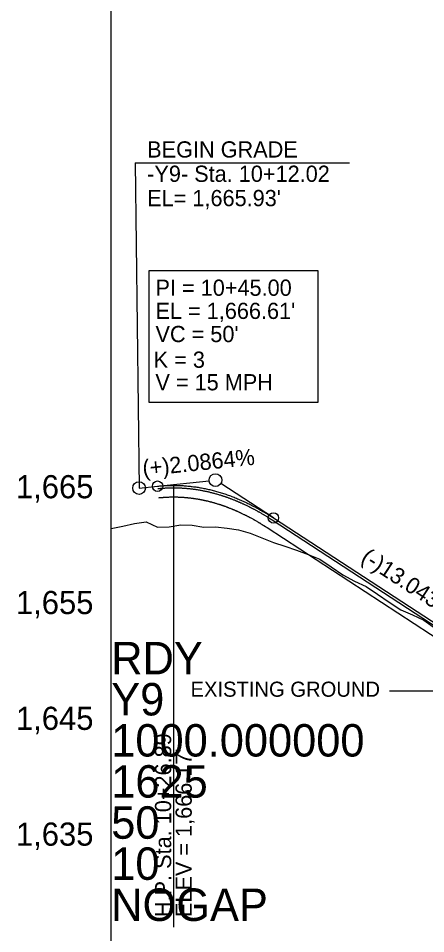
# Model space of a CAD drawing. Extents: x 498575 to 532350, y 405181 to 484585.
# Drawn here: x 505816.6 to 505992.5, y 449850.6 to 450245.8 of the extents above; entities that cross this region are included whole.
import ezdxf

# ---------------------------------------------------------------- set-up
doc = ezdxf.new("R2010")
doc.units = 0
for name, color, linetype in [('Exist Profile Cell', 7, 'Continuous'), ('Exist Vertical Profile Ground Line', 7, 'Continuous'), ('Exist Vertical Profile Vertical Axis Label', 7, 'Continuous'), ('Prop Grid Mask', 7, 'Continuous'), ('Prop PFL Text', 7, 'Continuous'), ('Prop Vertical Profile Curve Label', 7, 'Continuous'), ('Prop Vertical Profile Grade', 7, 'Continuous'), ('Prop Vertical Profile Grade Label', 7, 'Continuous'), ('Prop Vertical Profile Strip Grade', 7, 'Continuous'), ('Prop VPI Label', 7, 'Continuous'), ('Scratch_Level_5', 7, 'Continuous')]:
    doc.layers.add(name, color=color, linetype=linetype)

msp = doc.modelspace()

# ---------------------------------------------------------------- linework, layer by layer
at = {"layer": 'Exist Profile Cell'}
msp.add_line((505856.74, 449838.32), (505856.74, 451088.32), dxfattribs=at)
at = {"layer": 'Exist Vertical Profile Ground Line'}
msp.add_lwpolyline([(505856.74, 450025.46), (505861.74, 450026.58), (505866.74, 450027.62), (505871.74, 450028.47), (505876.74, 450026.08), (505881.74, 450026.18), (505886.74, 450027.05), (505891.74, 450026.9), (505896.74, 450026.1), (505901.74, 450026.27), (505906.74, 450025.71), (505911.74, 450024.91), (505916.74, 450023.57), (505921.74, 450021.47), (505926.74, 450019.48), (505931.74, 450017.95), (505936.74, 450016.24), (505941.74, 450014.28), (505946.74, 450012.24), (505951.74, 450009.02), (505956.74, 450005.57), (505961.74, 450002.85), (505966.74, 450000.46), (505971.74, 449997.13), (505976.74, 449993.78), (505981.74, 449990.43), (505986.74, 449988.29), (505991.74, 449986), (505996.74, 449982.39)], dxfattribs=at)
at = {"layer": 'Prop Grid Mask'}
msp.add_lwpolyline([(505872.99, 450080.05), (505946, 450080.05), (505946, 450136.83), (505872.99, 450136.83)], close=True, dxfattribs=at)
at = {"layer": 'Prop PFL Text'}
msp.add_line((505976.83, 449955.42), (505997.2, 449955.42), dxfattribs=at)
at = {"layer": 'Prop Vertical Profile Curve Label'}
for centre in [(505876.74, 450043.79), (505926.74, 450030.09)]:
    msp.add_circle(centre, 2.25, dxfattribs=at)
at = {"layer": 'Prop Vertical Profile Grade'}
for p, q in [((505868.76, 450042.96), (505876.74, 450043.79)), ((505926.74, 450030.09), (506021.74, 449968.14))]:
    msp.add_line(p, q, dxfattribs=at)
msp.add_spline([(505876.74, 450043.79), (505877.74, 450043.89), (505878.74, 450043.97), (505879.74, 450044.04), (505880.74, 450044.09), (505881.74, 450044.12), (505882.74, 450044.14), (505883.74, 450044.15), (505884.74, 450044.14), (505885.74, 450044.12), (505886.74, 450044.08), (505887.74, 450044.02), (505888.74, 450043.95), (505889.74, 450043.87), (505890.74, 450043.77), (505891.74, 450043.65), (505892.74, 450043.52), (505893.74, 450043.38), (505894.74, 450043.22), (505895.74, 450043.04), (505896.74, 450042.85), (505897.74, 450042.64), (505898.74, 450042.42), (505899.74, 450042.19), (505900.74, 450041.94), (505901.74, 450041.67), (505902.74, 450041.39), (505903.74, 450041.09), (505904.74, 450040.78), (505905.74, 450040.45), (505906.74, 450040.11), (505907.74, 450039.75), (505908.74, 450039.38), (505909.74, 450038.99), (505910.74, 450038.59), (505911.74, 450038.17), (505912.74, 450037.74), (505913.74, 450037.29), (505914.74, 450036.83), (505915.74, 450036.35), (505916.74, 450035.86), (505917.74, 450035.35), (505918.74, 450034.83), (505919.74, 450034.29), (505920.74, 450033.73), (505921.74, 450033.17), (505922.74, 450032.58), (505923.74, 450031.98), (505924.74, 450031.37), (505925.74, 450030.74), (505926.74, 450030.09)], degree=3, dxfattribs=at)
at = {"layer": 'Prop Vertical Profile Strip Grade'}
msp.add_line((505883.63, 450044.15), (505883.63, 449853.36), dxfattribs=at)
at = {"layer": 'Prop VPI Label'}
for p, q in [((505867.05, 450183.41), (505868.76, 450042.96)), ((505867.05, 450183.41), (505959.57, 450183.41)), ((505876.74, 450043.79), (505899, 450046.11)), ((505926.74, 450030.09), (505904.04, 450044.9))]:
    msp.add_line(p, q, dxfattribs=at)
for centre in [(505868.76, 450042.96), (505901.74, 450046.4)]:
    msp.add_circle(centre, 2.75, dxfattribs=at)
at = {"layer": 'Scratch_Level_5'}
for p, q in [((505924.01, 450025.91), (506019.01, 449963.95)), ((505926.17, 450029.22), (506021.17, 449967.26))]:
    msp.add_line(p, q, dxfattribs=at)
for points in [[(505876.84, 450042.75), (505877.11, 450042.78), (505877.42, 450042.81), (505877.75, 450042.84), (505877.8, 450042.85), (505877.83, 450042.85), (505877.83, 450042.85), (505877.84, 450042.85), (505877.85, 450042.85), (505877.92, 450042.86), (505878, 450042.87), (505878.2, 450042.88), (505878.33, 450042.89), (505878.53, 450042.91), (505878.6, 450042.91), (505878.7, 450042.92), (505878.74, 450042.92), (505878.78, 450042.93), (505878.79, 450042.93), (505878.81, 450042.93), (505878.82, 450042.93), (505878.84, 450042.93), (505878.99, 450042.94), (505879.42, 450042.97), (505879.82, 450043), (505880.63, 450043.04), (505881.18, 450043.06), (505882.26, 450043.1), (505882.8, 450043.11), (505883.89, 450043.11), (505884.43, 450043.11), (505885.51, 450043.08), (505886.06, 450043.07), (505887.14, 450043.02), (505887.68, 450042.98), (505888.76, 450042.91), (505889.3, 450042.86), (505890.38, 450042.76), (505890.92, 450042.7), (505891.73, 450042.61), (505892, 450042.57), (505892.54, 450042.5), (505892.81, 450042.46), (505893.61, 450042.35), (505894.15, 450042.26), (505895.22, 450042.08), (505895.75, 450041.98), (505896.55, 450041.83), (505896.82, 450041.77), (505897.35, 450041.66), (505897.61, 450041.61), (505898.41, 450041.43), (505898.94, 450041.31), (505899.73, 450041.12), (505899.99, 450041.05), (505900.52, 450040.92), (505900.78, 450040.85), (505901.57, 450040.64), (505902.09, 450040.49), (505903.14, 450040.19), (505903.66, 450040.03), (505904.43, 450039.78), (505904.69, 450039.7), (505905.21, 450039.53), (505905.47, 450039.45), (505905.98, 450039.27), (505906.24, 450039.18), (505906.75, 450039), (505907.26, 450038.82), (505907.77, 450038.63), (505908.28, 450038.44), (505908.54, 450038.34), (505909.3, 450038.05), (505909.8, 450037.85), (505910.43, 450037.59), (505910.56, 450037.54), (505910.81, 450037.44), (505911.19, 450037.28), (505911.56, 450037.12), (505912.06, 450036.9), (505912.31, 450036.79), (505912.81, 450036.57), (505913.31, 450036.35), (505913.8, 450036.12), (505914.29, 450035.89), (505914.54, 450035.77), (505915.28, 450035.42), (505915.77, 450035.18), (505916.38, 450034.88), (505916.5, 450034.82), (505916.74, 450034.69), (505917.1, 450034.51), (505917.47, 450034.32), (505917.95, 450034.07), (505918.19, 450033.94), (505918.67, 450033.68), (505919.15, 450033.42), (505919.75, 450033.1), (505920.11, 450032.9), (505920.34, 450032.76), (505920.46, 450032.7), (505921.06, 450032.36), (505921.53, 450032.09), (505922.23, 450031.67), (505922.47, 450031.53), (505922.94, 450031.25), (505923.4, 450030.97), (505923.9, 450030.67), (505924.16, 450030.5), (505924.19, 450030.48), (505924.2, 450030.48), (505924.21, 450030.47), (505924.24, 450030.45), (505924.32, 450030.4), (505924.39, 450030.36), (505924.56, 450030.25), (505924.68, 450030.18), (505924.91, 450030.03), (505925.02, 450029.96), (505925.14, 450029.88), (505925.15, 450029.88), (505925.16, 450029.87), (505925.17, 450029.87), (505925.17, 450029.86), (505925.19, 450029.85), (505925.23, 450029.82), (505925.34, 450029.76), (505925.65, 450029.55), (505925.94, 450029.37), (505926.18, 450029.22)], [(505877.22, 450038.81), (505877.5, 450038.84), (505877.8, 450038.87), (505878.13, 450038.9), (505878.19, 450038.91), (505878.21, 450038.91), (505878.22, 450038.91), (505878.22, 450038.91), (505878.22, 450038.91), (505878.22, 450038.91), (505878.23, 450038.91), (505878.24, 450038.91), (505878.3, 450038.92), (505878.35, 450038.92), (505878.52, 450038.94), (505878.64, 450038.95), (505878.83, 450038.96), (505878.9, 450038.97), (505879, 450038.97), (505879.03, 450038.98), (505879.07, 450038.98), (505879.09, 450038.98), (505879.1, 450038.98), (505879.11, 450038.98), (505879.11, 450038.98), (505879.11, 450038.98), (505879.11, 450038.98), (505879.13, 450038.98), (505879.27, 450038.99), (505879.67, 450039.02), (505880.05, 450039.05), (505880.56, 450039.07), (505880.82, 450039.09), (505881.33, 450039.11), (505881.58, 450039.12), (505882.34, 450039.14), (505882.85, 450039.15), (505883.87, 450039.15), (505884.38, 450039.15), (505885.4, 450039.13), (505885.91, 450039.11), (505886.67, 450039.07), (505886.93, 450039.06), (505887.44, 450039.03), (505887.69, 450039.02), (505888.45, 450038.96), (505888.96, 450038.92), (505889.59, 450038.86), (505889.72, 450038.85), (505889.97, 450038.82), (505890.1, 450038.81), (505890.48, 450038.77), (505890.99, 450038.71), (505891.5, 450038.64), (505891.87, 450038.59), (505892, 450038.58), (505892.25, 450038.54), (505892.63, 450038.49), (505893.01, 450038.43), (505893.39, 450038.37), (505893.52, 450038.35), (505893.77, 450038.31), (505893.89, 450038.29), (505894.52, 450038.18), (505895.03, 450038.09), (505895.59, 450037.98), (505895.66, 450037.97), (505895.78, 450037.94), (505895.84, 450037.93), (505896.03, 450037.89), (505896.41, 450037.82), (505896.78, 450037.74), (505897.28, 450037.63), (505897.53, 450037.57), (505898.03, 450037.46), (505898.53, 450037.34), (505899.03, 450037.21), (505899.34, 450037.13), (505899.4, 450037.12), (505899.53, 450037.09), (505899.59, 450037.07), (505899.77, 450037.02), (505900.15, 450036.92), (505900.52, 450036.82), (505901.01, 450036.68), (505901.26, 450036.61), (505902, 450036.4), (505902.49, 450036.25), (505903.05, 450036.07), (505903.11, 450036.05), (505903.23, 450036.01), (505903.29, 450035.99), (505903.47, 450035.94), (505903.84, 450035.82), (505904.21, 450035.69), (505904.58, 450035.57), (505904.7, 450035.53), (505904.94, 450035.44), (505905.06, 450035.4), (505905.43, 450035.27), (505905.91, 450035.1), (505906.4, 450034.92), (505906.7, 450034.81), (505906.76, 450034.78), (505906.88, 450034.74), (505906.94, 450034.72), (505907.12, 450034.65), (505907.24, 450034.6), (505907.85, 450034.37), (505908.33, 450034.18), (505908.87, 450033.96), (505908.93, 450033.93), (505909.05, 450033.88), (505909.23, 450033.81), (505909.65, 450033.63), (505910.12, 450033.43), (505910.48, 450033.27), (505910.66, 450033.2), (505910.72, 450033.17), (505910.84, 450033.12), (505911.13, 450032.99), (505911.67, 450032.75), (505912.14, 450032.53), (505912.43, 450032.39), (505912.49, 450032.36), (505912.58, 450032.32), (505912.61, 450032.31), (505912.67, 450032.28), (505912.81, 450032.21), (505913.43, 450031.92), (505914.02, 450031.63), (505914.54, 450031.37), (505914.6, 450031.34), (505914.71, 450031.28), (505914.89, 450031.19), (505915.3, 450030.99), (505915.76, 450030.75), (505916.13, 450030.55), (505916.28, 450030.47), (505916.34, 450030.44), (505916.37, 450030.43), (505916.45, 450030.38), (505916.74, 450030.23), (505917.26, 450029.95), (505917.83, 450029.63), (505918.17, 450029.44), (505918.32, 450029.36), (505918.34, 450029.35), (505918.4, 450029.31), (505918.49, 450029.26), (505919.03, 450028.96), (505919.54, 450028.66), (505920.05, 450028.36), (505920.1, 450028.33), (505920.22, 450028.27), (505920.27, 450028.23), (505920.44, 450028.13), (505920.78, 450027.93), (505921.34, 450027.59), (505921.82, 450027.3), (505922.07, 450027.14), (505922.1, 450027.12), (505922.1, 450027.12), (505922.1, 450027.12), (505922.11, 450027.12), (505922.12, 450027.11), (505922.15, 450027.09), (505922.17, 450027.08), (505922.24, 450027.03), (505922.3, 450027), (505922.47, 450026.89), (505922.58, 450026.82), (505922.79, 450026.69), (505922.89, 450026.62), (505923, 450026.56), (505923.01, 450026.55), (505923.02, 450026.54), (505923.03, 450026.54), (505923.03, 450026.54), (505923.03, 450026.54), (505923.03, 450026.54), (505923.03, 450026.54), (505923.03, 450026.54), (505923.05, 450026.53), (505923.09, 450026.5), (505923.19, 450026.43), (505923.51, 450026.23), (505923.8, 450026.04), (505924.03, 450025.89)]]:
    msp.add_open_spline(points, degree=3, dxfattribs=at)

# ---------------------------------------------------------------- texts
at = {"layer": 'Exist Profile Cell'}
for s, p in [('RDY', (505856.74, 449962.56)), ('Y9', (505856.74, 449944.81)), ('1000.000000', (505856.74, 449927.06)), ('1625', (505856.74, 449909.32)), ('50', (505856.74, 449891.57)), ('10', (505856.74, 449873.82)), ('NOGAP', (505856.74, 449856.07))]:
    msp.add_text(s, height=14, dxfattribs=at).set_placement(p)
at = {"layer": 'Exist Vertical Profile Vertical Axis Label'}
for s, p in [('1,665', (505815.59, 450038.57)), ('1,655', (505815.59, 449988.57)), ('1,645', (505815.59, 449938.57)), ('1,635', (505815.59, 449888.57))]:
    msp.add_text(s, height=10, dxfattribs=at).set_placement(p)
at = {"layer": 'Prop PFL Text'}
msp.add_text('EXISTING GROUND', height=6.5157, dxfattribs=at).set_placement((505890.96, 449952.88))
at = {"layer": 'Prop Vertical Profile Curve Label'}
for s, p in [("VC = 50'", (505875.84, 450106)), ('K = 3', (505875.06, 450094.92)), ('V = 15 MPH ', (505875.81, 450085.18))]:
    msp.add_text(s, height=7, dxfattribs=at).set_placement(p)
at = {"layer": 'Prop Vertical Profile Grade Label'}
for s, rotation, p in [('(+)2.0864%', 5.9556, (505870.58, 450048.04)), ('(-)13.0438%', 326.8879, (505964.06, 450011.57))]:
    msp.add_text(s, height=7, rotation=rotation, dxfattribs=at).set_placement(p)
at = {"layer": 'Prop Vertical Profile Strip Grade'}
for s, p in [('H.P. Sta. 10+26.89', (505882.61, 449857.74)), ("ELEV = 1,666.17'", (505891.49, 449857.74))]:
    msp.add_text(s, height=7, rotation=90, dxfattribs=at).set_placement(p)
at = {"layer": 'Prop VPI Label'}
for s, p in [('BEGIN GRADE', (505872.25, 450185.7)), ('-Y9- Sta. 10+12.02', (505872.25, 450175.2)), ("EL= 1,665.93'", (505872.25, 450164.7)), ('PI = 10+45.00', (505875.84, 450126)), ("EL = 1,666.61'", (505875.84, 450116))]:
    msp.add_text(s, height=7, dxfattribs=at).set_placement(p)

doc.saveas('drawing.dxf')
